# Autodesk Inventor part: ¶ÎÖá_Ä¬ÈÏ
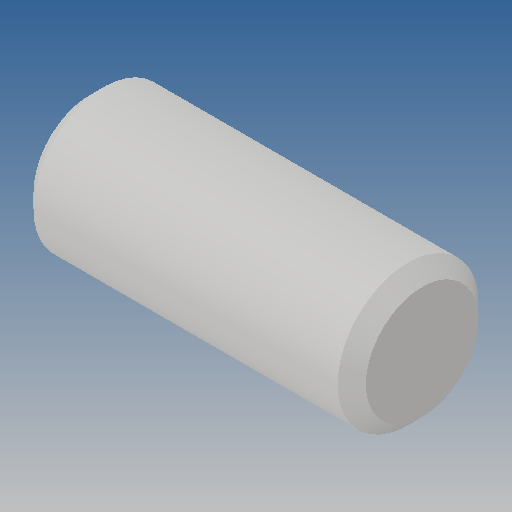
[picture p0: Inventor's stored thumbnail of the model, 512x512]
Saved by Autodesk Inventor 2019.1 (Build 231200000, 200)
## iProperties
Created: 2012-10
Part Number: ¶ÎÖá_Ä¬ÈÏ
Material: Ogólny
Document SubType Name: Modeling
Designer: CADENGINEERING4
Density: 1 g/cm^3
Appearance: Domyślna
Author: CADENGINEERING4
Revision Number: ÈÎºÎ
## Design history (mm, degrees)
feature "NONE"
node "Bryła1"
